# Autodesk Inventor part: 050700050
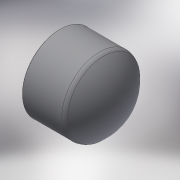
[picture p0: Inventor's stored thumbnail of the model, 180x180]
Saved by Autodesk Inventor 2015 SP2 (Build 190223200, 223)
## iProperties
Created: 2017-10
Part Number: 050700050
Material: Generic
Description: PLASSON CAP-CEMENT PVC 50
Document SubType Name: Modeling
Designer: KIM
Density: 1 g/cm^3
Appearance: Default
Author: KIM
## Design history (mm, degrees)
derived "050700.ipt"
feature "Solid1::050700.ipt"
tag "TaggingFeature1"
body "Solid1"
other parameters: "d7" = 0.5, "d9" = 58, "d28" = 1, "d29" = 31, "d31" = 45, "d32" = 47, "d33" = 32.55, "d34" = 5, "E_" = 58, "H_" = 47, "l_" = 31
